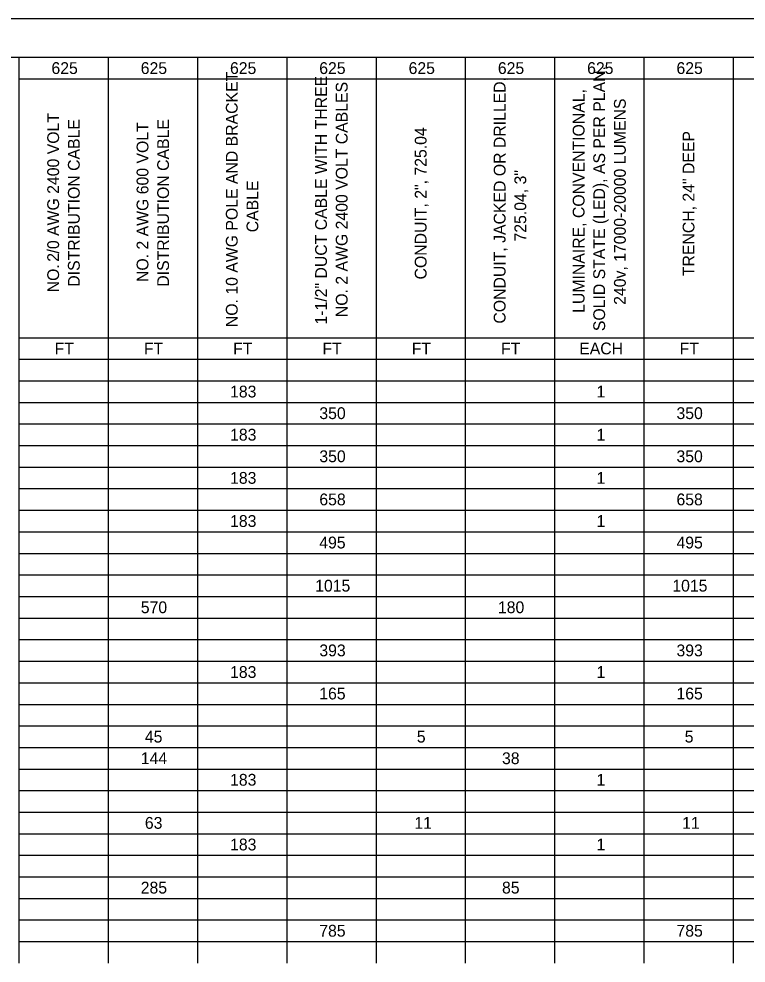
# Model space of a CAD drawing. Extents: x 0 to 34, y 0 to 22.
# Drawn here: x 14.57 to 24.03, y 9.72 to 22 of the extents above; entities that cross this region are included whole.
import ezdxf

# ---------------------------------------------------------------- set-up
doc = ezdxf.new("R2010")
doc.units = 0
for name, color, linetype in [('SH_Border', 7, 'Continuous'), ('SH_Cut_Line', 7, 'Continuous'), ('SH_Text', 7, 'Continuous')]:
    doc.layers.add(name, color=color, linetype=linetype)

msp = doc.modelspace()

# ---------------------------------------------------------------- linework, layer by layer
at = {"layer": 'SH_Border'}
msp.add_lwpolyline([(1.5, 21.5), (33.5, 21.5), (33.5, 0.5), (1.5, 0.5)], close=True, dxfattribs=at)
at = {"layer": 'SH_Cut_Line'}
msp.add_lwpolyline([(0, 0), (34, 0), (34, 22), (0, 22)], close=True, dxfattribs=at)
at = {"layer": 'SH_Text'}
for p, q in [((14.566, 21.5), (15.728, 21.5)), ((14.566, 21.5), (14.566, 21.219)), ((15.728, 21.5), (16.89, 21.5)), ((15.728, 21.5), (15.728, 21.219)), ((16.89, 21.5), (25.026, 21.5)), ((16.89, 21.5), (16.89, 21.219)), ((18.053, 21.5), (18.053, 21.219)), ((19.215, 21.5), (19.215, 21.219)), ((20.377, 21.5), (20.377, 21.219)), ((21.539, 21.5), (21.539, 21.219)), ((22.702, 21.5), (22.702, 21.219)), ((23.864, 21.5), (23.864, 21.219)), ((14.566, 21.219), (15.728, 21.219)), ((14.566, 21.219), (14.566, 20.939)), ((15.728, 21.219), (16.89, 21.219)), ((15.728, 21.219), (15.728, 20.939)), ((16.89, 21.219), (25.026, 21.219)), ((16.89, 21.219), (16.89, 20.939)), ((18.053, 21.219), (18.053, 20.939)), ((19.215, 21.219), (19.215, 20.939)), ((20.377, 21.219), (20.377, 20.939)), ((21.539, 21.219), (21.539, 20.939)), ((22.702, 21.219), (22.702, 20.939)), ((23.864, 21.219), (23.864, 20.939)), ((14.566, 20.939), (14.566, 20.658)), ((15.728, 20.939), (15.728, 20.658)), ((16.89, 20.939), (16.89, 20.658)), ((18.053, 20.939), (18.053, 20.658)), ((19.215, 20.939), (19.215, 20.658)), ((20.377, 20.939), (20.377, 20.658)), ((21.539, 20.939), (21.539, 20.658)), ((22.702, 20.939), (22.702, 20.658)), ((23.864, 20.939), (23.864, 20.658)), ((14.566, 20.658), (14.566, 20.378)), ((15.728, 20.658), (15.728, 20.378)), ((16.89, 20.658), (16.89, 20.378)), ((18.053, 20.658), (18.053, 20.378)), ((19.215, 20.658), (19.215, 20.378)), ((20.377, 20.658), (20.377, 20.378)), ((21.539, 20.658), (21.539, 20.378)), ((22.702, 20.658), (22.702, 20.378)), ((23.864, 20.658), (23.864, 20.378)), ((14.566, 20.378), (14.566, 20.097)), ((15.728, 20.378), (15.728, 20.097)), ((16.89, 20.378), (16.89, 20.097)), ((18.053, 20.378), (18.053, 20.097)), ((19.215, 20.378), (19.215, 20.097)), ((20.377, 20.378), (20.377, 20.097)), ((21.539, 20.378), (21.539, 20.097)), ((22.702, 20.378), (22.702, 20.097)), ((23.864, 20.378), (23.864, 20.097)), ((14.566, 20.097), (14.566, 19.817)), ((15.728, 20.097), (15.728, 19.817)), ((16.89, 20.097), (16.89, 19.817)), ((18.053, 20.097), (18.053, 19.817)), ((19.215, 20.097), (19.215, 19.817)), ((20.377, 20.097), (20.377, 19.817)), ((21.539, 20.097), (21.539, 19.817)), ((22.702, 20.097), (22.702, 19.817)), ((23.864, 20.097), (23.864, 19.817)), ((14.566, 19.817), (14.566, 19.536)), ((15.728, 19.817), (15.728, 19.536)), ((16.89, 19.817), (16.89, 19.536)), ((18.053, 19.817), (18.053, 19.536)), ((19.215, 19.817), (19.215, 19.536)), ((20.377, 19.817), (20.377, 19.536)), ((21.539, 19.817), (21.539, 19.536)), ((22.702, 19.817), (22.702, 19.536)), ((23.864, 19.817), (23.864, 19.536)), ((14.566, 19.536), (14.566, 18.975)), ((15.728, 19.536), (15.728, 18.975)), ((16.89, 19.536), (16.89, 18.975)), ((18.053, 19.536), (18.053, 18.975)), ((19.215, 19.536), (19.215, 18.975)), ((20.377, 19.536), (20.377, 18.975)), ((21.539, 19.536), (21.539, 18.975)), ((22.702, 19.536), (22.702, 18.975)), ((23.864, 19.536), (23.864, 18.975)), ((14.566, 18.975), (14.566, 18.133)), ((15.728, 18.975), (15.728, 18.133)), ((16.89, 18.975), (16.89, 18.133)), ((18.053, 18.975), (18.053, 18.133)), ((19.215, 18.975), (19.215, 18.133)), ((20.377, 18.975), (20.377, 18.133)), ((21.539, 18.975), (21.539, 18.133)), ((22.702, 18.975), (22.702, 18.133)), ((23.864, 18.975), (23.864, 18.133)), ((14.566, 18.133), (14.566, 17.853)), ((15.728, 18.133), (15.728, 17.853)), ((16.89, 18.133), (16.89, 17.853)), ((18.053, 18.133), (18.053, 17.853)), ((19.215, 18.133), (19.215, 17.853)), ((20.377, 18.133), (20.377, 17.853)), ((21.539, 18.133), (21.539, 17.853)), ((22.702, 18.133), (22.702, 17.853)), ((23.864, 18.133), (23.864, 17.853)), ((14.566, 17.853), (15.728, 17.853)), ((14.566, 17.853), (14.566, 17.292)), ((15.728, 17.853), (16.89, 17.853)), ((15.728, 17.853), (15.728, 17.292)), ((16.89, 17.853), (25.026, 17.853)), ((16.89, 17.853), (16.89, 17.292)), ((18.053, 17.853), (18.053, 17.292)), ((19.215, 17.853), (19.215, 17.292)), ((20.377, 17.853), (20.377, 17.292)), ((21.539, 17.853), (21.539, 17.292)), ((22.702, 17.853), (22.702, 17.292)), ((23.864, 17.853), (23.864, 17.292)), ((14.566, 17.572), (15.728, 17.572)), ((15.728, 17.572), (16.89, 17.572)), ((16.89, 17.572), (25.026, 17.572)), ((14.566, 17.292), (15.728, 17.292)), ((14.566, 17.292), (14.566, 17.011)), ((15.728, 17.292), (16.89, 17.292)), ((15.728, 17.292), (15.728, 17.011)), ((16.89, 17.292), (25.026, 17.292)), ((16.89, 17.292), (16.89, 17.011)), ((18.053, 17.292), (18.053, 17.011)), ((19.215, 17.292), (19.215, 17.011)), ((20.377, 17.292), (20.377, 17.011)), ((21.539, 17.292), (21.539, 17.011)), ((22.702, 17.292), (22.702, 17.011)), ((23.864, 17.292), (23.864, 17.011)), ((14.566, 17.011), (15.728, 17.011)), ((14.566, 17.011), (14.566, 15.889)), ((15.728, 17.011), (16.89, 17.011)), ((15.728, 17.011), (15.728, 15.889)), ((16.89, 17.011), (25.026, 17.011)), ((16.89, 17.011), (16.89, 15.889)), ((18.053, 17.011), (18.053, 15.889)), ((19.215, 17.011), (19.215, 15.889)), ((20.377, 17.011), (20.377, 15.889)), ((21.539, 17.011), (21.539, 15.889)), ((22.702, 17.011), (22.702, 15.889)), ((23.864, 17.011), (23.864, 15.889)), ((14.566, 16.731), (15.728, 16.731)), ((15.728, 16.731), (16.89, 16.731)), ((16.89, 16.731), (25.026, 16.731)), ((14.566, 16.45), (15.728, 16.45)), ((15.728, 16.45), (16.89, 16.45)), ((16.89, 16.45), (25.026, 16.45)), ((14.566, 16.17), (15.728, 16.17)), ((15.728, 16.17), (16.89, 16.17)), ((16.89, 16.17), (25.026, 16.17)), ((14.566, 15.889), (15.728, 15.889)), ((14.566, 15.889), (14.566, 15.608)), ((15.728, 15.889), (16.89, 15.889)), ((15.728, 15.889), (15.728, 15.608)), ((16.89, 15.889), (25.026, 15.889)), ((16.89, 15.889), (16.89, 15.608)), ((18.053, 15.889), (18.053, 15.608)), ((19.215, 15.889), (19.215, 15.608)), ((20.377, 15.889), (20.377, 15.608)), ((21.539, 15.889), (21.539, 15.608)), ((22.702, 15.889), (22.702, 15.608)), ((23.864, 15.889), (23.864, 15.608)), ((14.566, 15.608), (15.728, 15.608)), ((14.566, 15.608), (14.566, 15.047)), ((15.728, 15.608), (16.89, 15.608)), ((15.728, 15.608), (15.728, 15.047)), ((16.89, 15.608), (25.026, 15.608)), ((16.89, 15.608), (16.89, 15.047)), ((18.053, 15.608), (18.053, 15.047)), ((19.215, 15.608), (19.215, 15.047)), ((20.377, 15.608), (20.377, 15.047)), ((21.539, 15.608), (21.539, 15.047)), ((22.702, 15.608), (22.702, 15.047)), ((23.864, 15.608), (23.864, 15.047)), ((14.566, 15.328), (15.728, 15.328)), ((15.728, 15.328), (16.89, 15.328)), ((16.89, 15.328), (25.026, 15.328)), ((14.566, 15.047), (15.728, 15.047)), ((14.566, 15.047), (14.566, 14.486)), ((15.728, 15.047), (16.89, 15.047)), ((15.728, 15.047), (15.728, 14.486)), ((16.89, 15.047), (25.026, 15.047)), ((16.89, 15.047), (16.89, 14.486)), ((18.053, 15.047), (18.053, 14.486)), ((19.215, 15.047), (19.215, 14.486)), ((20.377, 15.047), (20.377, 14.486)), ((21.539, 15.047), (21.539, 14.486)), ((22.702, 15.047), (22.702, 14.486)), ((23.864, 15.047), (23.864, 14.486)), ((14.566, 14.767), (15.728, 14.767)), ((15.728, 14.767), (16.89, 14.767)), ((16.89, 14.767), (25.026, 14.767)), ((14.566, 14.486), (15.728, 14.486)), ((14.566, 14.486), (14.566, 14.206)), ((15.728, 14.486), (16.89, 14.486)), ((15.728, 14.486), (15.728, 14.206)), ((16.89, 14.486), (25.026, 14.486)), ((16.89, 14.486), (16.89, 14.206)), ((18.053, 14.486), (18.053, 14.206)), ((19.215, 14.486), (19.215, 14.206)), ((20.377, 14.486), (20.377, 14.206)), ((21.539, 14.486), (21.539, 14.206)), ((22.702, 14.486), (22.702, 14.206)), ((23.864, 14.486), (23.864, 14.206)), ((14.566, 14.206), (15.728, 14.206)), ((14.566, 14.206), (14.566, 13.645)), ((15.728, 14.206), (16.89, 14.206)), ((15.728, 14.206), (15.728, 13.645)), ((16.89, 14.206), (25.026, 14.206)), ((16.89, 14.206), (16.89, 13.645)), ((18.053, 14.206), (18.053, 13.645)), ((19.215, 14.206), (19.215, 13.645)), ((20.377, 14.206), (20.377, 13.645)), ((21.539, 14.206), (21.539, 13.645)), ((22.702, 14.206), (22.702, 13.645)), ((23.864, 14.206), (23.864, 13.645)), ((14.566, 13.925), (15.728, 13.925)), ((15.728, 13.925), (16.89, 13.925)), ((16.89, 13.925), (25.026, 13.925)), ((14.566, 13.645), (15.728, 13.645)), ((14.566, 13.645), (14.566, 13.364)), ((15.728, 13.645), (16.89, 13.645)), ((15.728, 13.645), (15.728, 13.364)), ((16.89, 13.645), (25.026, 13.645)), ((16.89, 13.645), (16.89, 13.364)), ((18.053, 13.645), (18.053, 13.364)), ((19.215, 13.645), (19.215, 13.364)), ((20.377, 13.645), (20.377, 13.364)), ((21.539, 13.645), (21.539, 13.364)), ((22.702, 13.645), (22.702, 13.364)), ((23.864, 13.645), (23.864, 13.364)), ((14.566, 13.364), (15.728, 13.364)), ((14.566, 13.364), (14.566, 12.522)), ((15.728, 13.364), (16.89, 13.364)), ((15.728, 13.364), (15.728, 12.522)), ((16.89, 13.364), (25.026, 13.364)), ((16.89, 13.364), (16.89, 12.522)), ((18.053, 13.364), (18.053, 12.522)), ((19.215, 13.364), (19.215, 12.522)), ((20.377, 13.364), (20.377, 12.522)), ((21.539, 13.364), (21.539, 12.522)), ((22.702, 13.364), (22.702, 12.522)), ((23.864, 13.364), (23.864, 12.522)), ((14.566, 13.083), (15.728, 13.083)), ((15.728, 13.083), (16.89, 13.083)), ((16.89, 13.083), (25.026, 13.083)), ((14.566, 12.803), (15.728, 12.803)), ((15.728, 12.803), (16.89, 12.803)), ((16.89, 12.803), (25.026, 12.803)), ((14.566, 12.522), (15.728, 12.522)), ((14.566, 12.522), (14.566, 11.961)), ((15.728, 12.522), (16.89, 12.522)), ((15.728, 12.522), (15.728, 11.961)), ((16.89, 12.522), (25.026, 12.522)), ((16.89, 12.522), (16.89, 11.961)), ((18.053, 12.522), (18.053, 11.961)), ((19.215, 12.522), (19.215, 11.961)), ((20.377, 12.522), (20.377, 11.961)), ((21.539, 12.522), (21.539, 11.961)), ((22.702, 12.522), (22.702, 11.961)), ((23.864, 12.522), (23.864, 11.961)), ((14.566, 12.242), (15.728, 12.242)), ((15.728, 12.242), (16.89, 12.242)), ((16.89, 12.242), (25.026, 12.242)), ((14.566, 11.961), (15.728, 11.961)), ((14.566, 11.961), (14.566, 11.12)), ((15.728, 11.961), (16.89, 11.961)), ((15.728, 11.961), (15.728, 11.12)), ((16.89, 11.961), (25.026, 11.961)), ((16.89, 11.961), (16.89, 11.12)), ((18.053, 11.961), (18.053, 11.12)), ((19.215, 11.961), (19.215, 11.12)), ((20.377, 11.961), (20.377, 11.12)), ((21.539, 11.961), (21.539, 11.12)), ((22.702, 11.961), (22.702, 11.12)), ((23.864, 11.961), (23.864, 11.12)), ((14.566, 11.681), (15.728, 11.681)), ((15.728, 11.681), (16.89, 11.681)), ((16.89, 11.681), (25.026, 11.681)), ((14.566, 11.4), (15.728, 11.4)), ((15.728, 11.4), (16.89, 11.4)), ((16.89, 11.4), (25.026, 11.4)), ((14.566, 11.12), (15.728, 11.12)), ((14.566, 11.12), (14.566, 10.558)), ((15.728, 11.12), (16.89, 11.12)), ((15.728, 11.12), (15.728, 10.558)), ((16.89, 11.12), (25.026, 11.12)), ((16.89, 11.12), (16.89, 10.558)), ((18.053, 11.12), (18.053, 10.558)), ((19.215, 11.12), (19.215, 10.558)), ((20.377, 11.12), (20.377, 10.558)), ((21.539, 11.12), (21.539, 10.558)), ((22.702, 11.12), (22.702, 10.558)), ((23.864, 11.12), (23.864, 10.558)), ((14.566, 10.839), (15.728, 10.839)), ((15.728, 10.839), (16.89, 10.839)), ((16.89, 10.839), (25.026, 10.839)), ((14.566, 10.558), (15.728, 10.558)), ((14.566, 10.558), (14.566, 9.717)), ((15.728, 10.558), (16.89, 10.558)), ((15.728, 10.558), (15.728, 9.717)), ((16.89, 10.558), (25.026, 10.558)), ((16.89, 10.558), (16.89, 9.717)), ((18.053, 10.558), (18.053, 9.717)), ((19.215, 10.558), (19.215, 9.717)), ((20.377, 10.558), (20.377, 9.717)), ((21.539, 10.558), (21.539, 9.717)), ((22.702, 10.558), (22.702, 9.717)), ((23.864, 10.558), (23.864, 9.717)), ((14.566, 10.278), (15.728, 10.278)), ((15.728, 10.278), (16.89, 10.278)), ((16.89, 10.278), (25.026, 10.278)), ((14.566, 9.997), (15.728, 9.997)), ((15.728, 9.997), (16.89, 9.997)), ((16.89, 9.997), (25.026, 9.997))]:
    msp.add_line(p, q, dxfattribs=at)

# ---------------------------------------------------------------- texts
for s, height, p in [('625', 0.1536, (14.99, 21.283)), ('625', 0.1536, (16.152, 21.283)), ('625', 0.1536, (17.314, 21.283)), ('625', 0.1536, (18.476, 21.283)), ('625', 0.1536, (19.639, 21.283)), ('625', 0.1536, (20.801, 21.283)), ('625', 0.1536, (21.963, 21.283)), ('625', 0.1536, (23.126, 21.283)), ('FT', 0.1536, (15.031, 17.636)), ('FT', 0.1536, (16.193, 17.636)), ('FT', 0.1536, (17.355, 17.636)), ('FT', 0.1536, (18.518, 17.636)), ('FT', 0.1536, (19.68, 17.636)), ('FT', 0.1536, (20.842, 17.636)), ('EACH', 0.1536, (21.86, 17.636)), ('FT', 0.1536, (23.167, 17.636)), ('183', 0.1536, (17.315, 17.075)), ('1', 0.154, (22.085, 17.075)), ('350', 0.1536, (18.477, 16.794)), ('350', 0.1536, (23.126, 16.794)), ('183', 0.1536, (17.315, 16.514)), ('1', 0.154, (22.085, 16.514)), ('350', 0.1536, (18.477, 16.233)), ('350', 0.1536, (23.126, 16.233)), ('183', 0.1536, (17.315, 15.952)), ('1', 0.154, (22.085, 15.952)), ('658', 0.1536, (18.477, 15.672)), ('658', 0.1536, (23.126, 15.672)), ('183', 0.1536, (17.315, 15.391)), ('1', 0.154, (22.085, 15.391)), ('495', 0.1536, (18.476, 15.111)), ('495', 0.1536, (23.126, 15.111)), ('1015', 0.1536, (18.423, 14.55)), ('1015', 0.1536, (23.072, 14.55)), ('570', 0.1536, (16.153, 14.269)), ('180', 0.1536, (20.802, 14.269)), ('393', 0.1536, (18.477, 13.708)), ('393', 0.1536, (23.126, 13.708)), ('183', 0.1536, (17.315, 13.427)), ('1', 0.154, (22.085, 13.427)), ('165', 0.1536, (18.476, 13.147)), ('165', 0.1536, (23.126, 13.147)), ('45', 0.1536, (16.206, 12.586)), ('5', 0.154, (19.746, 12.586)), ('5', 0.154, (23.233, 12.586)), ('144', 0.1536, (16.153, 12.305)), ('38', 0.1536, (20.855, 12.305)), ('183', 0.1536, (17.315, 12.025)), ('1', 0.154, (22.085, 12.025)), ('63', 0.1536, (16.206, 11.464)), ('11', 0.1536, (19.714, 11.464)), ('11', 0.1536, (23.2, 11.464)), ('183', 0.1536, (17.315, 11.183)), ('1', 0.154, (22.085, 11.183)), ('285', 0.1536, (16.152, 10.622)), ('85', 0.1536, (20.855, 10.622)), ('785', 0.1536, (18.476, 10.061)), ('785', 0.1536, (23.126, 10.061))]:
    msp.add_text(s, height=height, dxfattribs=at).set_placement(p)
for s, height, p in [('NO. 10 AWG POLE AND BRACKET ', 0.15364, (17.414, 17.99)), ('1-1/2" DUCT CABLE WITH THREE ', 0.15364, (18.576, 18.024)), ('SOLID STATE (LED), AS PER PLAN, ', 0.15364, (22.197, 17.938)), ('NO. 2 AWG 2400 VOLT CABLES', 0.15364, (18.845, 18.12)), ('CONDUIT, JACKED OR DRILLED, ', 0.15364, (20.901, 18.036)), ('LUMINAIRE, CONVENTIONAL, ', 0.15364, (21.929, 18.176)), ('240v, 17000-20000 LUMENS', 0.15364, (22.466, 18.28)), ('/0 AWG 2400 VOLT ', 0.15364, (15.089, 18.948)), ('DISTRIBUTION CABLE', 0.15364, (15.358, 18.516)), ('NO. 2 AWG 600 VOLT ', 0.15364, (16.252, 18.577)), ('DISTRIBUTION CABLE', 0.15364, (16.52, 18.516)), ('CONDUIT, 2", 725.04', 0.15364, (19.873, 18.61)), ('TRENCH, 24" DEEP', 0.15364, (23.36, 18.653)), ('725.04, 3"', 0.1536, (21.17, 19.104)), ('CABLE', 0.1536, (17.683, 19.224)), ('2', 0.154, (15.089, 18.84)), ('NO. ', 0.1536, (15.089, 18.443))]:
    msp.add_text(s, height=height, rotation=90, dxfattribs=at).set_placement(p)

doc.saveas('drawing.dxf')
